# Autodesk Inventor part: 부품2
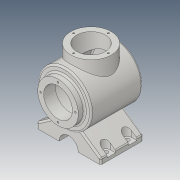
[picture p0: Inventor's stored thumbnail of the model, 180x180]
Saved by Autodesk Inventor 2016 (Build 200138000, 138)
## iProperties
Created: 2017-04
Part Number: 부품2
Material: 알루미늄 6061
Document SubType Name: Modeling
Designer: Administrator
Density: 2.7 g/cm^3
Appearance: 눈
Mass: 1651.3 g
Surface Area: 1071.48 cm^2
Volume: 611.591 cm^3
Author: Administrator
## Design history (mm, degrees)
sketch "스케치1"
  geometry: L1 (-60, 2.834)-(-60, 12.834); L2 (-60, 12.834)-(-17.156, 42.834); L3 (-17.156, 42.834)-(17.156, 42.834); L4 (17.156, 42.834)-(60, 12.834); L5 (60, 12.834)-(60, 2.834); L6 (60, 2.834)-(-60, 2.834); 1 further point
  constraints: 12 end point, 2 perpendicular, 1 parallel, 1 vertical
  dimensions: "d0" = 120 distance of L5.end L1.start; "d1" = 10 distance of L4.end L5.end; "d2" = 10 distance of L1.start L1.end; "d3" = 55 deg angle of L2 L1; "d4" = 55 deg angle of L5 L4; "d5" = 40 distance between parallel lines of L6 L3; "d25" = 60 distance from line of point (0, 0) L1
extrude "돌출1" new body sketch "스케치1" stored distance "d6" = 80; taper "d7" = 0 deg
sketch "스케치2"
  geometry: L1 (42.834, -40)-(2.834, -40) reference; L2 (2.834, -40)-(2.834, 40) reference; L3 (2.834, 40)-(42.834, 40) reference; L4 (42.834, 40)-(42.834, -40) reference; L5 (84.834, -60)-(84.834, 48); L6 (84.834, 48)-(134.834, 48); L7 (134.834, 48)-(134.834, -47.617); L8 (134.834, -60)-(84.834, -60); L9 (116.006, 53)-(59.177, 53); L10 (84.834, 48)-(84.834, 65.284); A1 r 113 centre (83.384, 52.991) between (84.834, -60) and (134.834, -47.617); 1 further point
  constraints: 12 end point, 3 perpendicular, 2 point on circle, 2 vertical, 1 centre point, 1 horizontal, 1 point on line
  dimensions: "d9" = 82 distance between parallel lines of L2 L5; "d10" = 100 diameter of L7 L5; "d11" = 8 distance between parallel lines of L3 L6; "d12" = 113 distance between parallel lines of L8 L9; "d16" = 113 radius of A1; "d108" = 108 distance from line of A1.start L6
revolve "회전1" sketch "스케치2" stored, may be unused: angle "d17" = 90 deg
sketch "스케치3"
  geometry: C1 r 50 at (0, 0) reference; C2 r 38 at (0, 0); 1 further point
  constraints: 1 centre point, 1 coincident
  dimensions: "d18" = 76 diameter of C2
extrude "돌출2" join sketch "스케치3" distance "d19" = 12; taper "d20" = 0 deg
node "작업 평면1"
sketch "스케치4"
  geometry: L1 (10, 8)-(110, 8) reference; C1 r 38 at (60, -42); 1 further point
  constraints: 1 centre point
  dimensions: "d91" = 76 diameter of C1; "d92" = 50 distance from line of L1 C1.centre
extrude "돌출3" join sketch "스케치4" stored distance "d23" = 12; taper "d24" = 0 deg
sketch "스케치5"
  geometry: L1 (-21.584, 39.732)-(-60, 12.834) reference; L2 (-60, 12.834)-(-60, 2.834) reference; L3 (-60, 2.834)-(60, 2.834) reference; L4 (60, 2.834)-(60, 12.834) reference; L5 (60, 12.834)-(21.584, 39.732) reference; A1 r 50 centre (0, 84.834) between (-21.584, 39.732) and (21.584, 39.732) reference; 1 further point
sketch "스케치6"
  geometry: L1 (-60, 2.834)-(60, 2.834) reference; C1 r 18 at (0, 2.834); 1 further point
  constraints: 1 centre point, 1 midpoint
  dimensions: "d26" = 36 diameter of C1
extrude "돌출4" cut sketch "스케치6" stored distance "d27" = 12; taper "d28" = 0 deg
node "작업 평면2"
sketch "스케치7"
  geometry: L1 (-87.129, -7.617)-(-87.129, 88) reference; L2 (-87.129, 88)-(-32.871, 88) reference; L3 (-32.871, 88)-(-32.871, -7.617) reference; L4 (-38.416, 0)-(-38.416, 80) reference; L5 (0, 80)-(-38.416, 80) reference; L6 (0, 80)-(0, 0) reference; L7 (-38.416, 0)-(0, 0) reference; L8 (-10, 52)-(0, 52); L9 (-10, 68)-(0, 68); L10 (-10, 28)-(0, 28); L11 (-10, 12)-(0, 12); A1 r 8 centre (-10, 60) between (-10, 68) and (-10, 52); A2 r 8 centre (-10, 20) between (-10, 28) and (-10, 12); 1 further point
  constraints: 8 end point, 4 point on circle, 4 point on line, 3 horizontal, 2 centre point, 1 horizontal alignment, 1 perpendicular, 1 tangent
  dimensions: "d30" = 16 diameter of A1; "d31" = 16 diameter of A2; "d32" = 20 vertical distance of point (-60, 40) A1.centre; "d33" = 20 vertical distance of A2.centre point (-60, 40); "d34" = 10 distance from line of L6 A2.centre; "d35" = 10 distance from line of L6 A1.centre
extrude "돌출5" cut sketch "스케치7" distance "d36" = 34; taper "d37" = 0 deg
sketch "스케치8"
  geometry: A1 r 8 centre (-10, -60) between (-10, -52) and (-10, -68) reference; 1 further point
hole "구멍1" sketch "스케치8" at (-10, -60) diameter "d38" = 8; stored, may be unused: countersink angle "d42" = 90 deg, drill point angle "d44" = 118 deg; dims "d39" = 6, "d40" = 4, "d41" = 2, "d43" = 8
sketch "스케치9"
  geometry: A1 r 8 centre (-10, -20) between (-10, -12) and (-10, -28) reference; 1 further point
hole "구멍2" sketch "스케치9" at (-10, -20) diameter "d45" = 8; stored, may be unused: countersink angle "d49" = 90 deg, drill point angle "d51" = 118 deg; dims "d46" = 6, "d47" = 4, "d48" = 2, "d50" = 8
node "작업 평면3"
sketch "스케치10"
  geometry: L1 (-20, 120)-(-8, 120) reference; L2 (-8, 120)-(-8, 132) reference; L3 (-8, 132)-(4, 132) reference; L4 (80, 132)-(87.617, 132) reference; L5 (87.617, 32)-(80, 32) reference; L6 (80, 32)-(80, 18) reference; L7 (80, 18)-(0, 18) reference; L8 (0, 18)-(0, 32) reference; L9 (0, 32)-(-8, 32) reference; L10 (-8, 32)-(-8, 44) reference; L11 (-8, 44)-(-20, 44) reference; L12 (-20, 44)-(-20, 120) reference; L13 (-20, 120)-(-20, 44) reference; L14 (-20, 82)-(89.999, 82); L15 (79.322, 122)-(5, 122); L16 (2, 119)-(2, 109); L17 (2, 109)-(-20, 109); L18 (4, 132)-(4, 147) reference; L19 (4, 147)-(80, 147) reference; L20 (80, 147)-(80, 132) reference; A1 r 113 centre (-12.991, 80.55) between (100, 82) and (87.617, 132) reference; A2 r 113 centre (-12.991, 83.45) between (87.617, 32) and (100, 82) reference; A3 r 103 centre (-12.991, 80.55) between (89.999, 82) and (82.091, 120.153); A4 r 102.942 centre (-12.991, 83.45) between (81.532, 42.676) and (82.092, 44); A5 r 3 centre (5, 119) between (5, 122) and (2, 119); A6 r 3 centre (79.322, 119) between (82.091, 120.153) and (79.322, 122); 2 further points
  constraints: 9 point on circle, 8 end point, 4 centre point, 4 tangent, 3 point on line, 2 perpendicular, 1 equal radius, 1 horizontal, 1 midpoint
  dimensions: "d52" = 22 distance of L16.end L17.end; "d55" = 10 radial gap between concentric circles of A1 A3; "d56" = 54 diameter of L17 L14; "d57" = 80 diameter of L15 L14; "d58" = 3 radius of A5
  node "절단 모서리 투영3"
sketch "스케치12"
  geometry: C1 r 27 at (0, 0) reference; 2 further points
  dimensions: "d63" = 32.5 distance of C1.centre point (0, 32.5)
hole "구멍3" sketch "스케치12" at (0, 32.5) diameter "d64" = 3.242; stored, may be unused: countersink angle "d68" = 90 deg, drill point angle "d70" = 118 deg; dims "d65" = 8, "d66" = 4, "d67" = 2, "d69" = 10
node "작업축1"
node "작업축2"
fillet "모깎기1" dims "d84" = 3
fillet "모깎기2" dims "d85" = 3
fillet "모깎기3" dims "d86" = 3
node "작업 평면4"
revolve "회전3" stored, may be unused: angle "d93" = 90 deg
sketch "스케치15"
  geometry: C1 r 38 at (0, 0) reference; C2 r 27 at (0, 0); 1 further point
  constraints: 1 centre point, 1 coincident
  dimensions: "d94" = 54 diameter of C2
extrude "돌출7" cut sketch "스케치15" stored distance "d95" = 10; taper "d96" = 0 deg
sketch "스케치16"
  geometry: C1 r 27 at (0, 0) reference; 2 further points
  dimensions: "d97" = 32.5 distance of point (0, 32.5) C1.centre
hole "구멍5" sketch "스케치16" at (0, 32.5) diameter "d98" = 3.242; stored, may be unused: countersink angle "d102" = 90 deg, drill point angle "d104" = 118 deg; dims "d99" = 8, "d100" = 4, "d101" = 2, "d103" = 10
node "작업축3"
node "작업 평면5"
sketch "스케치17"
  geometry: 1 further point
node "솔리드1"
mirror "대칭1"
pattern_circular "원형 패턴1" dims angle "d72" = 360 deg
pattern_circular "원형 패턴3" dims angle "d106" = 360 deg
node "투영된 루프1"
node "절단 모서리 투영1"
node "절단 모서리 투영2"
other parameters: "d15" = 226, "d21" = -147, "d109" = -108
